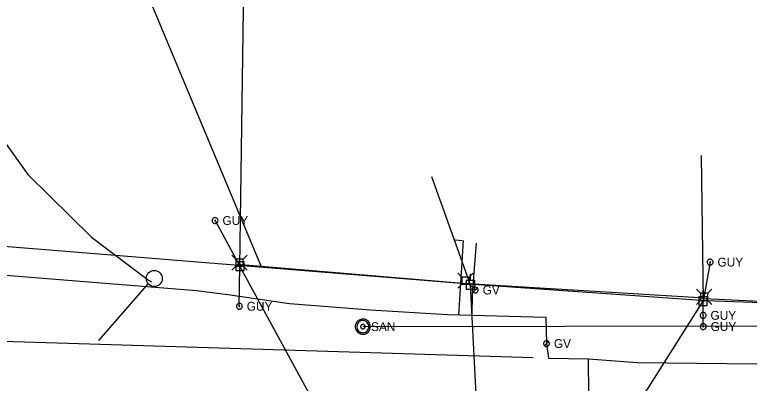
# Model space of a CAD drawing. Extents: x 596028 to 606371, y 330010 to 403088.
# Drawn here: x 604256.6 to 604575.9, y 349950 to 350110.5 of the extents above; entities that cross this region are included whole.
import ezdxf

# ---------------------------------------------------------------- set-up
doc = ezdxf.new("R2010")
doc.units = 0
for name, color, linetype in [('E_FTMS', 7, 'Continuous'), ('E_LTG_CID', 7, 'Continuous'), ('E_UTL_EGuyWire', 7, 'Continuous'), ('E_UTL_EPowerPole', 7, 'Continuous'), ('E_UTL_G', 7, 'Continuous'), ('E_UTL_G_UG', 7, 'Continuous'), ('E_UTL_Overhead', 7, 'Continuous'), ('E_UTL_SAN_MH', 7, 'Continuous'), ('E_UTL_SAN_UG', 7, 'Continuous'), ('E_UTL_T', 7, 'Continuous'), ('E_UTL_T_UG', 7, 'Continuous')]:
    doc.layers.add(name, color=color, linetype=linetype)

msp = doc.modelspace()

# ---------------------------------------------------------------- linework, layer by layer
at = {"layer": 'E_FTMS'}
msp.add_line((604314.6, 349993.43), (604293.03, 349968.63), dxfattribs=at)
msp.add_circle((604317.3, 349995.65), 3.5, dxfattribs=at)
at = {"layer": 'E_LTG_CID'}
msp.add_lwpolyline([(604241.43, 350070.91), (604242.24, 350068.97), (604262.41, 350040.93), (604290.01, 350013.57), (604314.86, 349994.86), (604316.12, 349994.26)], dxfattribs=at)
at = {"layer": 'E_UTL_EGuyWire'}
for p, q in [((604343.75, 350020.87), (604354.57, 350001.03)), ((604354.28, 349983.55), (604354.57, 350001.03)), ((604558.91, 350002.78), (604555.88, 349985.8)), ((604462.46, 349838.34), (604454.82, 349992.91)), ((604555.87, 349979.6), (604555.88, 349985.8)), ((604555.92, 349974.73), (604555.88, 349985.8))]:
    msp.add_line(p, q, dxfattribs=at)
for points in [[(604345.03, 350020.87), (604345.01, 350021.12), (604344.94, 350021.35), (604344.83, 350021.57), (604344.68, 350021.76), (604344.49, 350021.92), (604344.28, 350022.04), (604344.05, 350022.12), (604343.81, 350022.15), (604343.57, 350022.14), (604343.33, 350022.09), (604343.11, 350021.98), (604342.91, 350021.84), (604342.74, 350021.67), (604342.61, 350021.46), (604342.52, 350021.23), (604342.47, 350020.99), (604342.47, 350020.75), (604342.52, 350020.51), (604342.61, 350020.28), (604342.74, 350020.08), (604342.91, 350019.9), (604343.11, 350019.76), (604343.33, 350019.66), (604343.57, 350019.6), (604343.81, 350019.59), (604344.05, 350019.63), (604344.28, 350019.71), (604344.49, 350019.83), (604344.68, 350019.99), (604344.83, 350020.18), (604344.94, 350020.4), (604345.01, 350020.63), (604345.03, 350020.87)], [(604343.91, 350020.87), (604343.91, 350020.9), (604343.9, 350020.93), (604343.88, 350020.96), (604343.86, 350020.98), (604343.84, 350021), (604343.81, 350021.02), (604343.79, 350021.03), (604343.76, 350021.03), (604343.73, 350021.03), (604343.7, 350021.02), (604343.67, 350021.01), (604343.64, 350020.99), (604343.62, 350020.97), (604343.61, 350020.95), (604343.59, 350020.92), (604343.59, 350020.89), (604343.59, 350020.86), (604343.59, 350020.83), (604343.61, 350020.8), (604343.62, 350020.77), (604343.64, 350020.75), (604343.67, 350020.73), (604343.7, 350020.72), (604343.73, 350020.71), (604343.76, 350020.71), (604343.79, 350020.72), (604343.81, 350020.73), (604343.84, 350020.74), (604343.86, 350020.76), (604343.88, 350020.79), (604343.9, 350020.81), (604343.91, 350020.84), (604343.91, 350020.87)], [(604560.19, 350002.78), (604560.17, 350003.02), (604560.1, 350003.25), (604559.99, 350003.47), (604559.84, 350003.66), (604559.65, 350003.82), (604559.44, 350003.94), (604559.21, 350004.02), (604558.97, 350004.06), (604558.72, 350004.05), (604558.49, 350003.99), (604558.27, 350003.89), (604558.07, 350003.74), (604557.9, 350003.57), (604557.77, 350003.36), (604557.68, 350003.14), (604557.63, 350002.9), (604557.63, 350002.65), (604557.68, 350002.41), (604557.77, 350002.19), (604557.9, 350001.98), (604558.07, 350001.81), (604558.27, 350001.66), (604558.49, 350001.56), (604558.72, 350001.5), (604558.97, 350001.49), (604559.21, 350001.53), (604559.44, 350001.61), (604559.65, 350001.73), (604559.84, 350001.89), (604559.99, 350002.08), (604560.1, 350002.3), (604560.17, 350002.53), (604560.19, 350002.78)], [(604559.07, 350002.78), (604559.06, 350002.81), (604559.06, 350002.83), (604559.04, 350002.86), (604559.02, 350002.89), (604559, 350002.91), (604558.97, 350002.92), (604558.94, 350002.93), (604558.91, 350002.94), (604558.88, 350002.93), (604558.85, 350002.93), (604558.83, 350002.91), (604558.8, 350002.9), (604558.78, 350002.87), (604558.76, 350002.85), (604558.75, 350002.82), (604558.75, 350002.79), (604558.75, 350002.76), (604558.75, 350002.73), (604558.76, 350002.7), (604558.78, 350002.68), (604558.8, 350002.65), (604558.83, 350002.64), (604558.85, 350002.62), (604558.88, 350002.62), (604558.91, 350002.61), (604558.94, 350002.62), (604558.97, 350002.63), (604559, 350002.64), (604559.02, 350002.66), (604559.04, 350002.69), (604559.06, 350002.72), (604559.06, 350002.74), (604559.07, 350002.78)], [(604355.56, 349983.55), (604355.54, 349983.8), (604355.47, 349984.03), (604355.36, 349984.25), (604355.21, 349984.44), (604355.03, 349984.6), (604354.81, 349984.72), (604354.58, 349984.8), (604354.34, 349984.84), (604354.1, 349984.82), (604353.86, 349984.77), (604353.64, 349984.67), (604353.44, 349984.52), (604353.27, 349984.35), (604353.14, 349984.14), (604353.05, 349983.92), (604353, 349983.68), (604353, 349983.43), (604353.05, 349983.19), (604353.14, 349982.97), (604353.27, 349982.76), (604353.44, 349982.58), (604353.64, 349982.44), (604353.86, 349982.34), (604354.1, 349982.28), (604354.34, 349982.27), (604354.58, 349982.31), (604354.81, 349982.39), (604355.03, 349982.51), (604355.21, 349982.67), (604355.36, 349982.86), (604355.47, 349983.08), (604355.54, 349983.31), (604355.56, 349983.55)], [(604354.44, 349983.55), (604354.44, 349983.58), (604354.43, 349983.61), (604354.42, 349983.64), (604354.4, 349983.66), (604354.37, 349983.68), (604354.35, 349983.7), (604354.32, 349983.71), (604354.29, 349983.71), (604354.26, 349983.71), (604354.23, 349983.71), (604354.2, 349983.69), (604354.18, 349983.68), (604354.15, 349983.65), (604354.14, 349983.63), (604354.13, 349983.6), (604354.12, 349983.57), (604354.12, 349983.54), (604354.13, 349983.51), (604354.14, 349983.48), (604354.15, 349983.45), (604354.18, 349983.43), (604354.2, 349983.42), (604354.23, 349983.4), (604354.26, 349983.4), (604354.29, 349983.39), (604354.32, 349983.4), (604354.35, 349983.41), (604354.37, 349983.42), (604354.4, 349983.44), (604354.42, 349983.47), (604354.43, 349983.49), (604354.44, 349983.52), (604354.44, 349983.55)], [(604557.15, 349979.6), (604557.13, 349979.85), (604557.06, 349980.08), (604556.95, 349980.3), (604556.8, 349980.49), (604556.61, 349980.65), (604556.4, 349980.77), (604556.17, 349980.85), (604555.93, 349980.89), (604555.69, 349980.87), (604555.45, 349980.82), (604555.23, 349980.72), (604555.03, 349980.57), (604554.86, 349980.4), (604554.73, 349980.19), (604554.64, 349979.97), (604554.59, 349979.73), (604554.59, 349979.48), (604554.64, 349979.24), (604554.73, 349979.02), (604554.86, 349978.81), (604555.03, 349978.63), (604555.23, 349978.49), (604555.45, 349978.39), (604555.69, 349978.33), (604555.93, 349978.32), (604556.17, 349978.36), (604556.4, 349978.44), (604556.61, 349978.56), (604556.8, 349978.72), (604556.95, 349978.91), (604557.06, 349979.13), (604557.13, 349979.36), (604557.15, 349979.6)], [(604556.03, 349979.6), (604556.03, 349979.63), (604556.02, 349979.66), (604556, 349979.69), (604555.99, 349979.71), (604555.96, 349979.73), (604555.94, 349979.75), (604555.91, 349979.76), (604555.88, 349979.76), (604555.85, 349979.76), (604555.82, 349979.76), (604555.79, 349979.74), (604555.76, 349979.73), (604555.74, 349979.7), (604555.73, 349979.68), (604555.72, 349979.65), (604555.71, 349979.62), (604555.71, 349979.59), (604555.72, 349979.56), (604555.73, 349979.53), (604555.74, 349979.5), (604555.76, 349979.48), (604555.79, 349979.47), (604555.82, 349979.45), (604555.85, 349979.45), (604555.88, 349979.44), (604555.91, 349979.45), (604555.94, 349979.46), (604555.96, 349979.47), (604555.99, 349979.49), (604556, 349979.52), (604556.02, 349979.54), (604556.03, 349979.57), (604556.03, 349979.6)], [(604557.21, 349974.73), (604557.19, 349974.98), (604557.12, 349975.21), (604557, 349975.43), (604556.85, 349975.62), (604556.67, 349975.78), (604556.46, 349975.9), (604556.23, 349975.98), (604555.99, 349976.02), (604555.74, 349976.01), (604555.51, 349975.95), (604555.28, 349975.85), (604555.08, 349975.7), (604554.92, 349975.53), (604554.78, 349975.32), (604554.69, 349975.1), (604554.65, 349974.86), (604554.65, 349974.61), (604554.69, 349974.37), (604554.78, 349974.15), (604554.92, 349973.94), (604555.08, 349973.77), (604555.28, 349973.62), (604555.51, 349973.52), (604555.74, 349973.46), (604555.99, 349973.45), (604556.23, 349973.49), (604556.46, 349973.57), (604556.67, 349973.69), (604556.85, 349973.85), (604557, 349974.04), (604557.12, 349974.26), (604557.19, 349974.49), (604557.21, 349974.73)], [(604556.09, 349974.73), (604556.08, 349974.77), (604556.07, 349974.79), (604556.06, 349974.82), (604556.04, 349974.85), (604556.02, 349974.87), (604555.99, 349974.88), (604555.96, 349974.89), (604555.93, 349974.9), (604555.9, 349974.89), (604555.87, 349974.89), (604555.84, 349974.87), (604555.82, 349974.86), (604555.8, 349974.83), (604555.78, 349974.81), (604555.77, 349974.78), (604555.77, 349974.75), (604555.77, 349974.72), (604555.77, 349974.69), (604555.78, 349974.66), (604555.8, 349974.64), (604555.82, 349974.61), (604555.84, 349974.6), (604555.87, 349974.58), (604555.9, 349974.58), (604555.93, 349974.57), (604555.96, 349974.58), (604555.99, 349974.59), (604556.02, 349974.6), (604556.04, 349974.62), (604556.06, 349974.65), (604556.07, 349974.68), (604556.08, 349974.7), (604556.09, 349974.73)]]:
    msp.add_lwpolyline(points, dxfattribs=at)
at = {"layer": 'E_UTL_EPowerPole'}
for points in [[(604354.54, 350002.87), (604354.54, 350005.78)], [(604356.38, 350002.87), (604352.7, 350002.87)], [(604352.7, 350002.87), (604352.7, 349999.18)], [(604354.81, 350001.03), (604354.81, 350001.07), (604354.79, 350001.12), (604354.77, 350001.16), (604354.75, 350001.19), (604354.71, 350001.22), (604354.67, 350001.24), (604354.63, 350001.26), (604354.58, 350001.27), (604354.54, 350001.26), (604354.5, 350001.25), (604354.45, 350001.23), (604354.42, 350001.21), (604354.39, 350001.17), (604354.36, 350001.14), (604354.34, 350001.09), (604354.34, 350001.05), (604354.34, 350001), (604354.34, 350000.96), (604354.36, 350000.92), (604354.39, 350000.88), (604354.42, 350000.85), (604354.45, 350000.82), (604354.5, 350000.8), (604354.54, 350000.79), (604354.58, 350000.79), (604354.63, 350000.8), (604354.67, 350000.81), (604354.71, 350000.83), (604354.75, 350000.86), (604354.77, 350000.9), (604354.79, 350000.94), (604354.81, 350000.98), (604354.81, 350001.03)], [(604356.38, 349999.18), (604356.38, 350002.87)], [(604352.7, 349999.18), (604356.38, 349999.18)], [(604454.78, 349994.75), (604454.78, 349997.66)], [(604456.63, 349994.75), (604452.94, 349994.75)], [(604452.94, 349994.75), (604452.94, 349991.06)], [(604456.63, 349991.06), (604456.63, 349994.75)], [(604452.94, 349991.06), (604456.63, 349991.06)], [(604455.06, 349992.91), (604455.05, 349992.96), (604455.04, 349993), (604455.02, 349993.04), (604454.99, 349993.07), (604454.96, 349993.1), (604454.92, 349993.13), (604454.87, 349993.14), (604454.83, 349993.15), (604454.78, 349993.15), (604454.74, 349993.14), (604454.7, 349993.12), (604454.66, 349993.09), (604454.63, 349993.06), (604454.61, 349993.02), (604454.59, 349992.98), (604454.58, 349992.93), (604454.58, 349992.89), (604454.59, 349992.84), (604454.61, 349992.8), (604454.63, 349992.76), (604454.66, 349992.73), (604454.7, 349992.7), (604454.74, 349992.68), (604454.78, 349992.67), (604454.83, 349992.67), (604454.87, 349992.68), (604454.92, 349992.69), (604454.96, 349992.72), (604454.99, 349992.75), (604455.02, 349992.78), (604455.04, 349992.82), (604455.05, 349992.86), (604455.06, 349992.91)], [(604555.85, 349987.65), (604555.85, 349990.56)], [(604557.69, 349987.65), (604554.01, 349987.65)], [(604554.01, 349987.65), (604554.01, 349983.96)], [(604556.12, 349985.8), (604556.12, 349985.85), (604556.1, 349985.89), (604556.08, 349985.93), (604556.06, 349985.97), (604556.02, 349986), (604555.98, 349986.02), (604555.94, 349986.04), (604555.89, 349986.04), (604555.85, 349986.04), (604555.81, 349986.03), (604555.76, 349986.01), (604555.73, 349985.98), (604555.7, 349985.95), (604555.67, 349985.91), (604555.65, 349985.87), (604555.65, 349985.83), (604555.65, 349985.78), (604555.65, 349985.74), (604555.67, 349985.69), (604555.7, 349985.66), (604555.73, 349985.62), (604555.76, 349985.6), (604555.81, 349985.58), (604555.85, 349985.57), (604555.89, 349985.57), (604555.94, 349985.57), (604555.98, 349985.59), (604556.02, 349985.61), (604556.06, 349985.64), (604556.08, 349985.68), (604556.1, 349985.72), (604556.12, 349985.76), (604556.12, 349985.8)], [(604557.69, 349983.96), (604557.69, 349987.65)], [(604554.01, 349983.96), (604557.69, 349983.96)]]:
    msp.add_lwpolyline(points, dxfattribs=at)
at = {"layer": 'E_UTL_G'}
for points in [[(604458.11, 349990.64), (604458.09, 349990.88), (604458.02, 349991.11), (604457.91, 349991.33), (604457.76, 349991.52), (604457.57, 349991.68), (604457.36, 349991.8), (604457.13, 349991.88), (604456.89, 349991.92), (604456.65, 349991.91), (604456.41, 349991.85), (604456.19, 349991.75), (604455.99, 349991.61), (604455.82, 349991.43), (604455.69, 349991.22), (604455.6, 349991), (604455.55, 349990.76), (604455.55, 349990.51), (604455.6, 349990.27), (604455.69, 349990.05), (604455.82, 349989.84), (604455.99, 349989.67), (604456.19, 349989.52), (604456.41, 349989.42), (604456.65, 349989.37), (604456.89, 349989.35), (604457.13, 349989.39), (604457.36, 349989.47), (604457.57, 349989.59), (604457.76, 349989.75), (604457.91, 349989.94), (604458.02, 349990.16), (604458.09, 349990.39), (604458.11, 349990.64)], [(604455.92, 349989.73), (604457.74, 349991.54)], [(604489.08, 349967.33), (604489.06, 349967.57), (604488.99, 349967.81), (604488.88, 349968.02), (604488.73, 349968.22), (604488.54, 349968.38), (604488.33, 349968.5), (604488.1, 349968.58), (604487.86, 349968.61), (604487.62, 349968.6), (604487.38, 349968.54), (604487.16, 349968.44), (604486.96, 349968.3), (604486.79, 349968.12), (604486.66, 349967.92), (604486.57, 349967.69), (604486.52, 349967.45), (604486.52, 349967.21), (604486.57, 349966.97), (604486.66, 349966.74), (604486.79, 349966.54), (604486.96, 349966.36), (604487.16, 349966.22), (604487.38, 349966.12), (604487.62, 349966.06), (604487.86, 349966.05), (604488.1, 349966.08), (604488.33, 349966.16), (604488.54, 349966.29), (604488.73, 349966.45), (604488.88, 349966.64), (604488.99, 349966.85), (604489.06, 349967.09), (604489.08, 349967.33)], [(604486.89, 349966.42), (604488.71, 349968.24)]]:
    msp.add_lwpolyline(points, dxfattribs=at)
at = {"layer": 'E_UTL_G_UG'}
for points in [[(604451.12, 350012.03), (604448.06, 350012.3)], [(604449.76, 349979.74), (604451.65, 350012.12)], [(604455.46, 349979.58), (604455.62, 349988.98), (604457.36, 350011.04)], [(604252.85, 349997.07), (604335.69, 349990.44), (604349.27, 349988.73), (604376.12, 349984.81), (604411.24, 349982.02), (604444.79, 349980.04), (604487.55, 349978.81), (604487.8, 349967.33), (604488.65, 349961.03), (604506.03, 349960.73), (604527.14, 349959.03), (604592.13, 349958.39), (604651.99, 349959.87), (604682.48, 349959.49), (604732.67, 349957.01), (604787.08, 349955.9), (604797.56, 349955.68)], [(602826.9, 349977.26), (603315.02, 349970.71), (603331.6, 349993.52), (603526.72, 349990.73), (604482.07, 349961.23)], [(604504.65, 349836.13), (604504.4, 349847.54), (604505.16, 349873.83), (604506.5, 349914.62), (604506.33, 349929.59), (604506.03, 349960.73)]]:
    msp.add_lwpolyline(points, dxfattribs=at)
at = {"layer": 'E_UTL_Overhead'}
for p, q in [((604554.96, 350049.18), (604555.88, 349985.8)), ((604454.82, 349992.91), (604437.97, 350039.83)), ((604442.52, 349839.11), (604354.57, 350001.03)), ((604462.46, 349838.34), (604555.88, 349985.8))]:
    msp.add_line(p, q, dxfattribs=at)
for points in [[(604354.57, 350001.03), (604356.05, 350112.62), (604356.37, 350133.87), (604357.71, 350201.64), (604358.24, 350231.16)], [(603181.28, 350035.1), (603329.32, 350032.13), (603487.19, 350051.84), (603697.5, 350053.11), (603794.73, 350045.64), (603986.8, 350030.72), (604135.55, 350019.1), (604355.8, 350001.36), (604456.04, 349993.24), (604557.11, 349986.14), (604654.49, 349982.64), (604747.33, 349981.14), (604855.96, 349980.06), (604969.76, 349979.4), (605156.33, 349975.18)]]:
    msp.add_lwpolyline(points, dxfattribs=at)
at = {"layer": 'E_UTL_SAN_MH'}
for points in [[(604411.28, 349974.7), (604411.22, 349975.33), (604411.04, 349975.93), (604410.75, 349976.48), (604410.37, 349976.98), (604409.89, 349977.39), (604409.35, 349977.7), (604408.76, 349977.91), (604408.14, 349978), (604407.51, 349977.97), (604406.9, 349977.82), (604406.33, 349977.56), (604405.82, 349977.19), (604405.38, 349976.74), (604405.05, 349976.21), (604404.81, 349975.63), (604404.69, 349975.01), (604404.69, 349974.39), (604404.81, 349973.77), (604405.05, 349973.19), (604405.38, 349972.66), (604405.82, 349972.21), (604406.33, 349971.84), (604406.9, 349971.58), (604407.51, 349971.43), (604408.14, 349971.4), (604408.76, 349971.49), (604409.35, 349971.7), (604409.89, 349972.01), (604410.37, 349972.42), (604410.75, 349972.92), (604411.04, 349973.47), (604411.22, 349974.08), (604411.28, 349974.7)], [(604410.62, 349974.7), (604410.57, 349975.2), (604410.43, 349975.68), (604410.2, 349976.13), (604409.89, 349976.52), (604409.51, 349976.85), (604409.07, 349977.1), (604408.6, 349977.27), (604408.1, 349977.34), (604407.6, 349977.31), (604407.11, 349977.2), (604406.66, 349976.99), (604406.25, 349976.7), (604405.9, 349976.33), (604405.63, 349975.91), (604405.45, 349975.44), (604405.35, 349974.95), (604405.35, 349974.45), (604405.45, 349973.96), (604405.63, 349973.49), (604405.9, 349973.07), (604406.25, 349972.71), (604406.66, 349972.41), (604407.11, 349972.21), (604407.6, 349972.09), (604408.1, 349972.06), (604408.6, 349972.14), (604409.07, 349972.3), (604409.51, 349972.55), (604409.89, 349972.88), (604410.2, 349973.27), (604410.43, 349973.72), (604410.57, 349974.2), (604410.62, 349974.7)], [(604408.97, 349974.7), (604408.95, 349974.89), (604408.9, 349975.07), (604408.81, 349975.24), (604408.69, 349975.38), (604408.55, 349975.51), (604408.39, 349975.6), (604408.21, 349975.66), (604408.03, 349975.69), (604407.84, 349975.68), (604407.65, 349975.64), (604407.48, 349975.56), (604407.33, 349975.45), (604407.2, 349975.31), (604407.1, 349975.15), (604407.03, 349974.98), (604406.99, 349974.79), (604406.99, 349974.61), (604407.03, 349974.42), (604407.1, 349974.25), (604407.2, 349974.09), (604407.33, 349973.95), (604407.48, 349973.84), (604407.65, 349973.77), (604407.84, 349973.72), (604408.03, 349973.71), (604408.21, 349973.74), (604408.39, 349973.8), (604408.55, 349973.89), (604408.69, 349974.02), (604408.81, 349974.17), (604408.9, 349974.33), (604408.95, 349974.51), (604408.97, 349974.7)]]:
    msp.add_lwpolyline(points, dxfattribs=at)
at = {"layer": 'E_UTL_SAN_UG'}
msp.add_line((604407.98, 349974.7), (604737.68, 349975.25), dxfattribs=at)
at = {"layer": 'E_UTL_T'}
for points in [[(604352.81, 350004.06), (604351.05, 350005.82)], [(604355.9, 350004.06), (604352.81, 350004.06)], [(604352.81, 350004.06), (604352.81, 350000.97)], [(604355.9, 350004.06), (604357.65, 350005.82)], [(604355.9, 350000.97), (604355.9, 350004.06)], [(604352.81, 350000.97), (604351.05, 349999.22)], [(604352.81, 350000.97), (604355.9, 350000.97)], [(604355.9, 350000.97), (604357.65, 349999.22)], [(604451.04, 349996.26), (604449.29, 349998.01)], [(604454.14, 349996.26), (604455.89, 349998.01)], [(604454.14, 349996.26), (604451.04, 349996.26)], [(604451.04, 349996.26), (604451.04, 349993.16)], [(604454.14, 349993.16), (604454.14, 349996.26)], [(604451.04, 349993.16), (604449.29, 349991.41)], [(604451.04, 349993.16), (604454.14, 349993.16)], [(604454.14, 349993.16), (604455.89, 349991.41)], [(604554.8, 349989.2), (604553.04, 349990.95)], [(604557.89, 349989.2), (604554.8, 349989.2)], [(604554.8, 349989.2), (604554.8, 349986.11)], [(604557.89, 349989.2), (604559.64, 349990.95)], [(604557.89, 349986.11), (604557.89, 349989.2)], [(604554.8, 349986.11), (604553.04, 349984.35)], [(604554.8, 349986.11), (604557.89, 349986.11)], [(604557.89, 349986.11), (604559.64, 349984.35)]]:
    msp.add_lwpolyline(points, dxfattribs=at)
at = {"layer": 'E_UTL_T_UG'}
for points in [[(604363.72, 350000.97), (604313.64, 350121.3), (604199.71, 350403.53), (604218.29, 350415.71)], [(604353.29, 350001.85), (604451.46, 349993.55), (604554.09, 349987.33), (604556.31, 349986.95), (604580.52, 349985.83)]]:
    msp.add_lwpolyline(points, dxfattribs=at)

# ---------------------------------------------------------------- texts
at = {"layer": 'E_UTL_EGuyWire'}
for p in [(604346.96, 350018.95), (604562.12, 350000.85), (604357.49, 349981.63), (604559.08, 349977.68), (604559.13, 349972.81)]:
    msp.add_text('GUY', height=3.85, dxfattribs=at).set_placement(p)
at = {"layer": 'E_UTL_G'}
for p in [(604460.04, 349988.71), (604491.01, 349965.41)]:
    msp.add_text('GV', height=3.85, dxfattribs=at).set_placement(p)
at = {"layer": 'E_UTL_SAN_MH'}
msp.add_text('SAN', height=3.849, dxfattribs=at).set_placement((604411.54, 349972.76))

doc.saveas('drawing.dxf')
